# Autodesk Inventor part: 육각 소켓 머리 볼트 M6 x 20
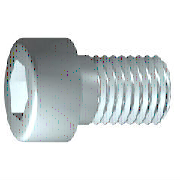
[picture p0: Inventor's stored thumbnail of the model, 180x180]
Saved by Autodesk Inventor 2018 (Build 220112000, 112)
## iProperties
IsCustomPart: 1
Created: 2012-02
Part Number: 육각 소켓 머리 볼트 M6 x 20
Material: 강철, 연강
Description: 6각 소켓 머리 캡 나사
Document SubType Name: Modeling
Standard: ISO 4762
Designer: mdu-01
Standard Revision: Fourth edition 2004-03-01
Standards Organization: ISO
Language: ko-KR
Size Designation: M6 x 20
Categories: <MemberInstance><Categories><Category DisplayName="조임쇠" InternalName="e4da775c-781d-43d5-af7c-5136215cf5a6" Mnemonic="FSTN"><Category DisplayName="볼트" InternalN
Density: 7.75 g/cm^3
Appearance: 강철
Author: mdu-01
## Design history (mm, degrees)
sketch "스케치1"
  geometry: L1 (-1.333, 0)-(20, 0); L2 (20, 0)-(20, 3); L3 (20, 3)-(2.5, 3); L4 (2.5, 3)-(1.886, 3); L5 (1.886, 3)-(0, 3); L6 (0, 3)-(0, 5); L7 (0, 5)-(-6, 5); L8 (-6, 5)-(-6, 2.887); L9 (-6, 2.887)-(-3, 2.887); L10 (-3, 2.887)-(-1.333, 0); L11 (-11.2, 0)-(25.2, 0) reference; L12 (0, -1)-(0, 6) reference; L13 (2.5, 3)-(0, 3)
  constraints: 22 end point, 6 parallel, 2 collinear, 2 perpendicular, 1 horizontal, 1 point on line
  dimensions: "d1" = 17.5 distance from line of L3.end L2 (= GEL); "d2" = 0.61355 distance of L4.end L3.end (computed from GAL); "d3" = 6 distance between parallel lines of L8 L6 (= KOH); "d4" = 3 distance of L8.end L9.end (= INTI); "d5" = 60 deg angle of L10 L1; "d6" = 6 diameter of L3 L1 (= GD); "d7" = 6 diameter of L5 L1 (= BDM); "d8" = 5.7735 diameter of L9 L1 (= 1.1547 x SW); "d9" = 10 diameter of L7 L1 (= KOD); "d26" = 20 distance between parallel lines of L12 L2 (= NLG)
revolve "본체" sketch "스케치1" stored, may be unused: angle "d10" = 90 deg
sketch "스케치2"
  geometry: L1 (0, -7)-(0, 7) reference; L2 (-7, 0)-(7, 0) reference; L3 (2.887, 0)-(1.443, -2.5); L4 (1.443, -2.5)-(-1.443, -2.5); L5 (-1.443, -2.5)-(-2.887, 0); L6 (-2.887, 0)-(-1.443, 2.5); L7 (-1.443, 2.5)-(1.443, 2.5); L8 (1.443, 2.5)-(2.887, 0); 2 further points
  constraints: 12 end point, 1 coincident, 1 horizontal alignment, 1 point on line, 12 other
extrude "슬롯" join sketch "스케치2" stored distance "d11" = 10; taper "d12" = 0 deg
workplane "Work Plane1"
fillet "Fillet2" dims "d30" = 0.1 (= R)
body "Solid1"
fillet "모깎기1" dims "d17" = 0.6 (= RR)
feature "스레드" dims "d13" = 17.5 (= GEL), "d14" = 0
chamfer "모따기1" distance "d15" = 0.61345 (= -0.5 x SPD + 0.5 x GD); stored, may be unused: second distance "d16" = 0.61345 (= GUL), angle "d27" = 45 deg
other parameters: "GD" = 6 [user parameter; used in 2 equation terms], "NLG" = 20 [user parameter; used in 1 equation term], "GEL" = 17.5 [user parameter; used in 2 equation terms], "KOD" = 10 [user parameter; used in 1 equation term], "KOH" = 6 [user parameter; used in 1 equation term], "INTI" = 3 [user parameter; used in 1 equation term], "GAL" = 0.61345 (= 0.61345 x PTC) [user parameter; used in 1 equation term], "GUL" = 0.61345 (= 0.61345 x PTC) [user parameter; used in 1 equation term], "BDM" = 6 (= NND) [user parameter; used in 1 equation term], "SW" = 5 [user parameter; used in 2 equation terms], "RR" = 0.6 [user parameter; used in 1 equation term], "SPD" = 4.7731 (= NND - 1.2269 x PTC) [user parameter; used in 1 equation term], "d19" = 0, "d28" = 0, "d29" = 0, "R" = 0.1 [user parameter; used in 1 equation term], "TOA" = 30 deg [user parameter], "GD1" = 4.7731 (= THREADDIA - 1.2269 x PTC) [user parameter], "THREADDIA" = 6 [user parameter; used in 1 equation term], "FAWI" = 45 deg [user parameter], "PTC" = 1 [user parameter; used in 5 equation terms], "NND" = 6 [user parameter; used in 2 equation terms], "E0" = 5.775 (= 1.155 x SW) [user parameter]
